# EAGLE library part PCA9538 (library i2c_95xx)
8bit I2C-Bus-Expander with Interrupt and Reset
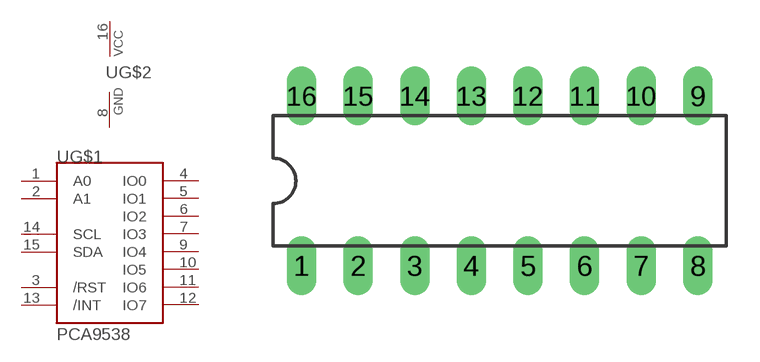
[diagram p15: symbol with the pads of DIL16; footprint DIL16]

Designator prefix -; gates G$1=PCA9538 G$2=PWRN

## PCA9538  [DIL16]
1  G$1:A0
2  G$1:A1
3  G$1:/RST
4  G$1:IO0
5  G$1:IO1
6  G$1:IO2
7  G$1:IO3
8  G$2:GND  pwr
9  G$1:IO4
10  G$1:IO5
11  G$1:IO6
12  G$1:IO7
13  G$1:/INT
14  G$1:SCL
15  G$1:SDA
16  G$2:VCC  pwr

## Footprint DIL16 (pad centres in mm)
drill 0.813 long: 1 -8.89,-3.81; 2 -6.35,-3.81; 3 -3.81,-3.81; 4 -1.27,-3.81; 5 1.27,-3.81; 6 3.81,-3.81; 7 6.35,-3.81; 8 8.89,-3.81; 9 8.89,3.81; 10 6.35,3.81; 11 3.81,3.81; 12 1.27,3.81; 13 -1.27,3.81; 14 -3.81,3.81; 15 -6.35,3.81; 16 -8.89,3.81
